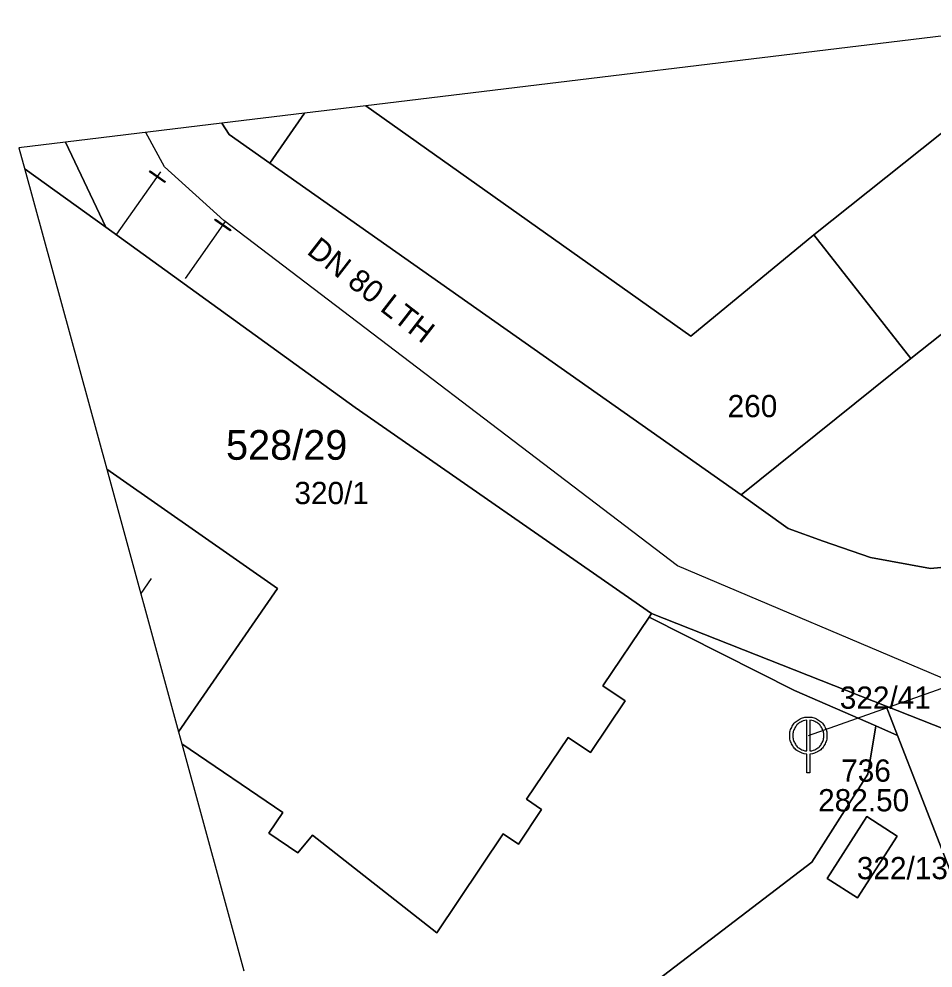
# Model space of a CAD drawing. Extents: x -571312 to -571060, y -1087128 to -1086933.
# Drawn here: x -571312.1 to -571250.5, y -1087007.2 to -1086943.2 of the extents above; entities that cross this region are included whole.
import ezdxf

# ---------------------------------------------------------------- set-up
doc = ezdxf.new("R2010")
doc.units = 0
for name, color, linetype in [('Adresní místo-text', 7, 'Continuous'), ('Armatura vodovodní', 7, 'Continuous'), ('Default', 7, 'Continuous'), ('Kanalizační přípojka', 7, 'Continuous'), ('Kanalizační stoka', 7, 'Continuous'), ('Kanalizační šachta', 7, 'Continuous'), ('Parcela-polygon', 7, 'Continuous'), ('Parcela-text', 7, 'Continuous'), ('Popis šachty', 7, 'Continuous'), ('Vodovodní přípojka', 7, 'Continuous'), ('Vodovodní řad', 7, 'Continuous'), ('Řad vodovodní popis', 7, 'Continuous')]:
    doc.layers.add(name, color=color, linetype=linetype)

msp = doc.modelspace()

# ---------------------------------------------------------------- linework, layer by layer
at = {"layer": 'Armatura vodovodní'}
for points in [[(-571303.274, -1086953.473), (-571302.251, -1086954.191), (-571302.295, -1086954.255), (-571303.319, -1086953.537), (-571303.274, -1086953.473)], [(-571297.888, -1086957.514), (-571298.91, -1086956.794), (-571298.865, -1086956.73), (-571297.843, -1086957.45), (-571297.888, -1086957.514)]]:
    msp.add_lwpolyline(points, dxfattribs=at)
at = {"layer": 'Default'}
for points in [[(-571259.013, -1086992.788), (-571259.271, -1086992.77), (-571259.533, -1086992.624), (-571259.83, -1086992.46), (-571259.995, -1086992.163), (-571260.16, -1086991.865), (-571260.16, -1086991.54), (-571260.16, -1086991.213), (-571259.992, -1086990.913), (-571259.823, -1086990.612), (-571259.525, -1086990.451), (-571259.227, -1086990.29), (-571258.91, -1086990.29), (-571258.595, -1086990.29), (-571258.296, -1086990.451), (-571257.997, -1086990.612), (-571257.828, -1086990.913), (-571257.66, -1086991.213), (-571257.66, -1086991.54), (-571257.66, -1086991.865), (-571257.825, -1086992.163), (-571257.99, -1086992.46), (-571258.287, -1086992.624), (-571258.549, -1086992.77), (-571258.807, -1086992.788)], [(-571259.013, -1086990.502), (-571259.21, -1086990.519), (-571259.425, -1086990.634), (-571259.674, -1086990.769), (-571259.813, -1086991.019), (-571259.952, -1086991.269), (-571259.952, -1086991.54), (-571259.952, -1086991.811), (-571259.816, -1086992.058), (-571259.679, -1086992.304), (-571259.43, -1086992.441), (-571259.218, -1086992.561), (-571259.013, -1086992.575)], [(-571258.807, -1086992.575), (-571258.602, -1086992.561), (-571258.388, -1086992.441), (-571258.141, -1086992.304), (-571258.004, -1086992.058), (-571257.868, -1086991.811), (-571257.868, -1086991.54), (-571257.868, -1086991.269), (-571258.008, -1086991.019), (-571258.148, -1086990.769), (-571258.397, -1086990.634), (-571258.61, -1086990.519), (-571258.807, -1086990.502)]]:
    msp.add_open_spline(points, degree=3, dxfattribs=at)
at = {"layer": 'Kanalizační přípojka'}
msp.add_line((-571303.197, -1086980.962), (-571303.906, -1086981.973), dxfattribs=at)
at = {"layer": 'Kanalizační stoka'}
msp.add_lwpolyline([(-571258.91, -1086991.54), (-571219.76, -1086977.67), (-571208.5, -1086973.24)], dxfattribs=at)
at = {"layer": 'Kanalizační šachta'}
for points in [[(-571259.013, -1086992.575), (-571259.013, -1086990.502)], [(-571258.807, -1086990.502), (-571258.807, -1086992.575)], [(-571258.807, -1086992.788), (-571258.807, -1086994.04), (-571259.013, -1086994.04), (-571259.013, -1086992.788)]]:
    msp.add_lwpolyline(points, dxfattribs=at)
at = {"layer": 'Parcela-polygon'}
for p, q in [((-571240.477, -1086943.242), (-571288.74, -1086949.093)), ((-571288.74, -1086949.093), (-571292.862, -1086949.593)), ((-571292.862, -1086949.593), (-571298.444, -1086950.27)), ((-571298.444, -1086950.27), (-571308.971, -1086951.546)), ((-571311.715, -1086953.393), (-571306.199, -1086973.58)), ((-571306.199, -1086973.58), (-571301.36, -1086991.291)), ((-571301.36, -1086991.291), (-571301.139, -1086992.1)), ((-571301.139, -1086992.1), (-571296.961, -1087007.388))]:
    msp.add_line(p, q, dxfattribs=at)
for points in [[(-571288.74, -1086949.093), (-571266.82, -1086964.63), (-571258.55, -1086957.8), (-571240.45, -1086943.4), (-571240.477, -1086943.242)], [(-571292.862, -1086949.593), (-571295.2, -1086952.96), (-571263.43, -1086975.32), (-571252.01, -1086966.13), (-571258.55, -1086957.8), (-571266.82, -1086964.63), (-571288.74, -1086949.093)], [(-571298.444, -1086950.27), (-571297.94, -1086951.03), (-571295.2, -1086952.96), (-571292.862, -1086949.593)], [(-571247.22, -1086979.94), (-571250.67, -1086980.27), (-571254.71, -1086979.53), (-571257.91, -1086978.43), (-571260.26, -1086977.58), (-571263.43, -1086975.32), (-571295.2, -1086952.96), (-571297.94, -1086951.03), (-571298.444, -1086950.27)], [(-571308.971, -1086951.546), (-571312.115, -1086951.927), (-571311.715, -1086953.393)], [(-571311.715, -1086953.393), (-571311.69, -1086953.36), (-571306.25, -1086957.27), (-571308.971, -1086951.546)], [(-571308.971, -1086951.546), (-571306.25, -1086957.27), (-571289.46, -1086969.43), (-571269.48, -1086983.31), (-571253.67, -1086989.56), (-571249.74, -1086991.11), (-571231.55, -1086984.26), (-571212.55, -1086977.39), (-571191.88, -1086968.96), (-571178.41, -1086963.67), (-571168.71, -1086959.87), (-571150.45, -1086953.94)], [(-571301.139, -1086992.1), (-571294.32, -1086996.72), (-571295.27, -1086998.11), (-571293.32, -1086999.43), (-571292.34, -1086998.24), (-571283.95, -1087004.83), (-571279.47, -1086998.16), (-571278.45, -1086998.85), (-571276.89, -1086996.52), (-571277.9, -1086995.83), (-571275.1, -1086991.66), (-571273.59, -1086992.67), (-571271.26, -1086989.2), (-571272.76, -1086988.18), (-571269.65, -1086983.55), (-571269.48, -1086983.31), (-571289.46, -1086969.43), (-571306.25, -1086957.27), (-571311.69, -1086953.36), (-571311.715, -1086953.393)], [(-571306.199, -1086973.58), (-571305.3, -1086974.21), (-571294.69, -1086981.63), (-571301.36, -1086991.291)], [(-571301.36, -1086991.291), (-571294.69, -1086981.63), (-571305.3, -1086974.21), (-571306.199, -1086973.58)], [(-571290.277, -1087027.098), (-571285.9, -1087020.87), (-571258.67, -1087000.06), (-571254.9, -1086994.13), (-571254.35, -1086990.89), (-571259.84, -1086988.49), (-571269.65, -1086983.55), (-571272.76, -1086988.18), (-571271.26, -1086989.2), (-571273.59, -1086992.67), (-571275.1, -1086991.66), (-571277.9, -1086995.83), (-571276.89, -1086996.52), (-571278.45, -1086998.85), (-571279.47, -1086998.16), (-571283.95, -1087004.83), (-571292.34, -1086998.24), (-571293.32, -1086999.43), (-571295.27, -1086998.11), (-571294.32, -1086996.72), (-571301.139, -1086992.1)]]:
    msp.add_lwpolyline(points, dxfattribs=at)
for points in [[(-571240.45, -1086943.4), (-571258.55, -1086957.8), (-571252.01, -1086966.13), (-571244.18, -1086959.93), (-571242.08, -1086958.27), (-571233.81, -1086951.73)], [(-571252.01, -1086966.13), (-571263.43, -1086975.32), (-571260.26, -1086977.58), (-571257.91, -1086978.43), (-571254.71, -1086979.53), (-571250.67, -1086980.27), (-571247.22, -1086979.94), (-571245.21, -1086979.4), (-571232.95, -1086975.24), (-571244.18, -1086959.93)], [(-571252.89, -1086991.54), (-571253.67, -1086989.56), (-571269.48, -1086983.31), (-571269.65, -1086983.55), (-571259.84, -1086988.49), (-571254.35, -1086990.89)], [(-571223.27, -1087054.35), (-571220.52, -1087052.71), (-571221.22, -1087051.48), (-571224.28, -1087046.14), (-571236.3, -1087025.16), (-571245.11, -1087002.85), (-571249.74, -1086991.11), (-571253.67, -1086989.56), (-571252.89, -1086991.54), (-571239.35, -1087026.31), (-571236.49, -1087031.3)], [(-571280.58, -1087024.78), (-571275.83, -1087028.1), (-571251.17, -1087045.35), (-571243.07, -1087038.57), (-571255.12, -1087027.8), (-571244.8, -1087016.38), (-571238.33, -1087033.34), (-571236.49, -1087031.3), (-571239.35, -1087026.31), (-571252.89, -1086991.54), (-571254.35, -1086990.89), (-571254.9, -1086994.13), (-571258.67, -1087000.06), (-571285.9, -1087020.87), (-571280.44, -1087024.63)], [(-571254.97, -1086997), (-571252.92, -1086998.31), (-571255.6, -1087002.48), (-571257.65, -1087001.17)], [(-571254.97, -1086997), (-571257.65, -1087001.17), (-571255.6, -1087002.48), (-571252.92, -1086998.31)]]:
    msp.add_lwpolyline(points, close=True, dxfattribs=at)
at = {"layer": 'Vodovodní přípojka'}
for p, q in [((-571305.511, -1086957.749), (-571302.553, -1086953.533)), ((-571298.212, -1086956.889), (-571300.919, -1086960.731))]:
    msp.add_line(p, q, dxfattribs=at)
at = {"layer": 'Vodovodní řad'}
msp.add_lwpolyline([(-571118.52, -1087001.2), (-571118.67, -1087000.053), (-571123.745, -1086988.554), (-571132.766, -1086954.96), (-571134.366, -1086951.47), (-571139.458, -1086950.161), (-571144.547, -1086950.9), (-571169.366, -1086958.786), (-571197.91, -1086970.492), (-571213.143, -1086976.341), (-571239.84, -1086984.572), (-571249.273, -1086987.925), (-571267.719, -1086980.097), (-571298.302, -1086956.821), (-571302.312, -1086953.213), (-571303.56, -1086950.89)], dxfattribs=at)

# ---------------------------------------------------------------- texts
at = {"layer": 'Adresní místo-text'}
msp.add_text('528/29', height=2, dxfattribs=at).set_placement((-571298.161, -1086972.95))
at = {"layer": 'Parcela-text'}
for s, p in [('260', (-571264.35, -1086970.08)), ('320/1', (-571293.55, -1086975.94)), ('322/41', (-571256.79, -1086989.73)), ('322/13', (-571255.64, -1087001.22))]:
    msp.add_text(s, height=1.5, dxfattribs=at).set_placement(p)
at = {"layer": 'Popis šachty'}
for s, p in [('736', (-571256.696, -1086994.646)), ('282.50', (-571258.249, -1086996.646))]:
    msp.add_text(s, height=1.5, dxfattribs=at).set_placement(p)
at = {"layer": 'Řad vodovodní popis'}
msp.add_text('DN 80 LTH', height=1.5, rotation=322.14735, dxfattribs=at).set_placement((-571292.784, -1086959.022))

doc.saveas('drawing.dxf')
